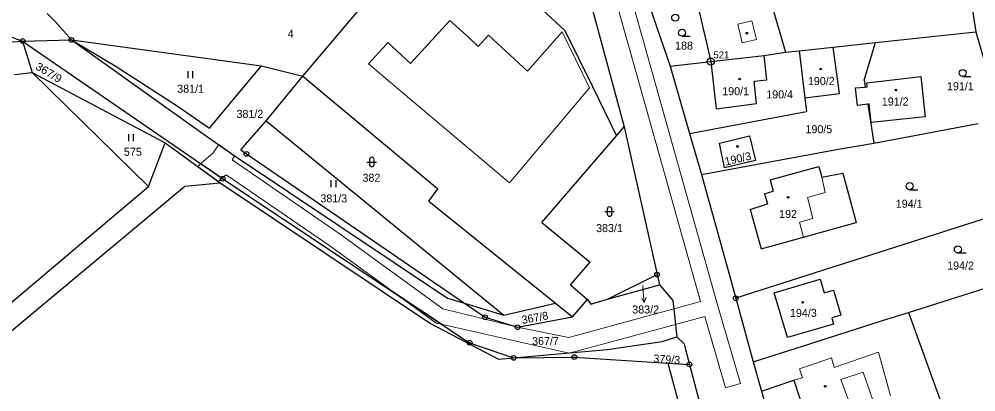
# Model space of a CAD drawing. Extents: x -633485 to -630509, y -1112692 to -1108818.
# Drawn here: x -632090.4 to -631887.2, y -1111932.7 to -1111853.5 of the extents above; entities that cross this region are included whole.
import ezdxf
from ezdxf.enums import TextEntityAlignment as Align

# ---------------------------------------------------------------- set-up
doc = ezdxf.new("R2010")
doc.units = 0
doc.header["$LTSCALE"] = 0.68
for name, color, linetype, lineweight in [('1', 7, 'Continuous', 25), ('13', 7, 'Continuous', 13), ('3', 7, 'Continuous', 25), ('4', 7, 'Continuous', 13), ('5', 7, 'Continuous', 25), ('7', 7, 'Continuous', 13), ('8', 7, 'Continuous', 25)]:
    doc.layers.add(name, color=color, linetype=linetype, lineweight=lineweight)
doc.layers.add('2', color=7, linetype='Continuous')

msp = doc.modelspace()

# ---------------------------------------------------------------- linework, layer by layer
at = {"layer": '1'}
for p, q in [((-631998.22, -1111834.02), (-631974.46, -1111855.89)), ((-631935.68, -1111832.67), (-631927.63, -1111860.54)), ((-631971.67, -1111840.26), (-631961.88, -1111876.36)), ((-632030.12, -1111865.6), (-632010.39, -1111842.25)), ((-631957.85, -1111846.76), (-631952.09, -1111863.51)), ((-631888.32, -1111848.82), (-631887.21, -1111856.22)), ((-632084.43, -1111852.32), (-632082.76, -1111853.97)), ((-631946.06, -1111851.62), (-631943.49, -1111862.52)), ((-632099.62, -1111854.48), (-632089.68, -1111858.15)), ((-632082.76, -1111853.97), (-632079.31, -1111857.93)), ((-631974.46, -1111855.89), (-631968.62, -1111867.8)), ((-631908.53, -1111858.5), (-631887.21, -1111856.22)), ((-631887.21, -1111856.22), (-631881.84, -1111874.72)), ((-632201.81, -1111865.84), (-632089.68, -1111858.15)), ((-632089.68, -1111858.15), (-632079.31, -1111857.93)), ((-632089.68, -1111858.15), (-632047.16, -1111887.42)), ((-632089.68, -1111858.15), (-632087.66, -1111864.83)), ((-632079.31, -1111857.93), (-632051.1, -1111877.99)), ((-632079.31, -1111857.93), (-632038.9, -1111863.4)), ((-632079.31, -1111857.93), (-632070, -1111863.44)), ((-631917.48, -1111859.49), (-631908.53, -1111858.5)), ((-631910.94, -1111866.46), (-631908.53, -1111858.5)), ((-631932.13, -1111861.24), (-631927.63, -1111860.54)), ((-631927.63, -1111860.54), (-631924.68, -1111860.27)), ((-631924.68, -1111860.27), (-631917.48, -1111859.49)), ((-631916.18, -1111869.33), (-631917.48, -1111859.49)), ((-632070, -1111863.44), (-632056.83, -1111871.95)), ((-632050, -1111876.68), (-632038.9, -1111863.4)), ((-632038.9, -1111863.4), (-632030.12, -1111865.6)), ((-632091.38, -1111865.28), (-632087.66, -1111864.83)), ((-632087.66, -1111864.83), (-632062.95, -1111889.09)), ((-632087.66, -1111864.83), (-632059.38, -1111879.77)), ((-632037.91, -1111875.15), (-632030.12, -1111865.6)), ((-632030.12, -1111865.6), (-632001.49, -1111889.6)), ((-631910.94, -1111866.46), (-631910.71, -1111867.94)), ((-631910.36, -1111867.01), (-631898.88, -1111865.72)), ((-631968.62, -1111867.8), (-631963.49, -1111878.29)), ((-631912.75, -1111868.12), (-631910.71, -1111867.94)), ((-631912.33, -1111871.84), (-631912.75, -1111868.12)), ((-631910.71, -1111867.94), (-631910.28, -1111867.9)), ((-631910.28, -1111867.9), (-631910.36, -1111867.01)), ((-631923.49, -1111870.22), (-631923.15, -1111873.1)), ((-632056.83, -1111871.95), (-632050, -1111876.68)), ((-631910.15, -1111871.6), (-631912.33, -1111871.84)), ((-631909.86, -1111871.57), (-631910.15, -1111871.6)), ((-631910.15, -1111871.6), (-631908.88, -1111879.83)), ((-631909.44, -1111875.46), (-631909.86, -1111871.57)), ((-632043.35, -1111881.28), (-632037.91, -1111875.15)), ((-632037.91, -1111875.15), (-631987.42, -1111916.44)), ((-631963.49, -1111878.29), (-631961.88, -1111876.36)), ((-631961.88, -1111876.36), (-631954.88, -1111907.8)), ((-631908.88, -1111879.83), (-631886.67, -1111875.7)), ((-632051.1, -1111877.99), (-632044.54, -1111882.62)), ((-631979.37, -1111896.75), (-631963.49, -1111878.29)), ((-631947.98, -1111877.8), (-631945.47, -1111886.5)), ((-632062.95, -1111889.09), (-632059.38, -1111879.77)), ((-632059.38, -1111879.77), (-632047.68, -1111888.29)), ((-631916.79, -1111881.23), (-631908.88, -1111879.83)), ((-632044.54, -1111882.62), (-631999.43, -1111912.79)), ((-632043.35, -1111881.28), (-632042.12, -1111882.14)), ((-632042.12, -1111882.14), (-631995.78, -1111913.9)), ((-631945.47, -1111886.5), (-631916.79, -1111881.23)), ((-631930.91, -1111887.65), (-631920.51, -1111884.81)), ((-631920.51, -1111884.81), (-631919.87, -1111887.08)), ((-631945.47, -1111886.5), (-631938.19, -1111912.84)), ((-631919.87, -1111887.08), (-631915.44, -1111886.26)), ((-631915.44, -1111886.26), (-631912.62, -1111896.71)), ((-632096.11, -1111923.1), (-632055.22, -1111889.02)), ((-632055.22, -1111889.02), (-632047.68, -1111888.29)), ((-632047.68, -1111888.29), (-632003.04, -1111918.16)), ((-632047.16, -1111887.42), (-631994.71, -1111922.29)), ((-631930.91, -1111887.65), (-631930.22, -1111890.09)), ((-632099.6, -1111920.09), (-632062.95, -1111889.09)), ((-632003.39, -1111892.19), (-632001.49, -1111889.6)), ((-631932.06, -1111890.61), (-631930.22, -1111890.09)), ((-631932.06, -1111890.61), (-631931.45, -1111892.78)), ((-632003.39, -1111892.19), (-631976.45, -1111913.88)), ((-631874.74, -1111892.53), (-631938.19, -1111912.84)), ((-631935.13, -1111893.95), (-631931.45, -1111892.78)), ((-631935.13, -1111893.95), (-631932.76, -1111902.35)), ((-631979.37, -1111896.75), (-631969.12, -1111905.15)), ((-631923.78, -1111899.82), (-631912.62, -1111896.71)), ((-631932.76, -1111902.35), (-631923.78, -1111899.82)), ((-631973.27, -1111909.97), (-631969.12, -1111905.15)), ((-631901.48, -1111915.84), (-631872.64, -1111906.66)), ((-631965.4, -1111913.05), (-631954.88, -1111907.8)), ((-631954.88, -1111907.8), (-631954.4, -1111909.97)), ((-631973.27, -1111909.97), (-631969.71, -1111913.06)), ((-631965.4, -1111913.05), (-631954.4, -1111909.97)), ((-631954.4, -1111909.97), (-631951.57, -1111913.27)), ((-631999.43, -1111912.79), (-631995.78, -1111913.9)), ((-631972.86, -1111916.77), (-631969.71, -1111913.06)), ((-631969.71, -1111913.06), (-631968.99, -1111914.05)), ((-631968.99, -1111914.05), (-631965.4, -1111913.05)), ((-631951.57, -1111913.27), (-631950.69, -1111921.01)), ((-631938.19, -1111912.84), (-631934.46, -1111926.33)), ((-631995.78, -1111913.9), (-631991.45, -1111916.87)), ((-631995.78, -1111913.9), (-631987.42, -1111916.44)), ((-631987.42, -1111916.44), (-631976.45, -1111913.88)), ((-631976.45, -1111913.88), (-631972.86, -1111916.77)), ((-631991.45, -1111916.87), (-631984.52, -1111918.98)), ((-631984.52, -1111918.98), (-631972.86, -1111916.77)), ((-631907, -1111917.59), (-631901.48, -1111915.84)), ((-631901.48, -1111915.84), (-631891.55, -1111943.23)), ((-632003.04, -1111918.16), (-631988.55, -1111925.79)), ((-631923.82, -1111922.95), (-631907, -1111917.59)), ((-631953.83, -1111922.04), (-631950.69, -1111921.01)), ((-631950.69, -1111921.01), (-631949.16, -1111922.53)), ((-631994.71, -1111922.29), (-631985.37, -1111925.51)), ((-631965.48, -1111923.75), (-631953.83, -1111922.04)), ((-631949.16, -1111922.53), (-631948.85, -1111923.69)), ((-631934.46, -1111926.33), (-631923.82, -1111922.95)), ((-631988.55, -1111925.79), (-631985.37, -1111925.51)), ((-631985.37, -1111925.51), (-631965.48, -1111923.75)), ((-631985.37, -1111925.51), (-631972.49, -1111925.33)), ((-631972.49, -1111925.33), (-631952.6, -1111926.6)), ((-631948.85, -1111923.69), (-631948.02, -1111926.89)), ((-631952.6, -1111926.6), (-631948.02, -1111926.89)), ((-631952.6, -1111926.6), (-631946.86, -1111947.99)), ((-631948.02, -1111926.89), (-631914.27, -1112055.54)), ((-631934.46, -1111926.33), (-631932.7, -1111932.56)), ((-631932.7, -1111932.56), (-631925.86, -1111930.24)), ((-631925.86, -1111930.24), (-631922.8, -1111939.4)), ((-631932.7, -1111932.56), (-631926.51, -1111954.39))]:
    msp.add_line(p, q, dxfattribs=at)
for points in [[(-631924.68, -1111860.27), (-631923.49, -1111870.22), (-631916.18, -1111869.33)], [(-631952.09, -1111863.51), (-631943.49, -1111862.52), (-631932.13, -1111861.24)], [(-631943.49, -1111862.52), (-631942.36, -1111872.57), (-631933.76, -1111871.46), (-631934.3, -1111866.72), (-631931.55, -1111866.41), (-631932.13, -1111861.24)], [(-631952.09, -1111863.51), (-631947.98, -1111877.8), (-631923.15, -1111873.1)], [(-631898.88, -1111865.72), (-631897.93, -1111874.24), (-631909.44, -1111875.46)], [(-631927.19, -1111921.2), (-631930.04, -1111911.66), (-631920.24, -1111908.77), (-631919.38, -1111911.7)], [(-631919.38, -1111911.7), (-631917.41, -1111911.11), (-631915.84, -1111916.43), (-631917.8, -1111917.01)], [(-631917.8, -1111917.01), (-631917.43, -1111918.3), (-631927.19, -1111921.2)]]:
    msp.add_lwpolyline(points, dxfattribs=at)
msp.add_lwpolyline([(-631940.59, -1111885.13), (-631941.67, -1111879.84), (-631935.25, -1111878.27), (-631933.97, -1111883.52)], close=True, dxfattribs=at)
at = {"layer": '13'}
msp.add_lwpolyline([(-631964.38, -1111846.95), (-631945.65, -1111913.51), (-631951.36, -1111915.07), (-631973.62, -1111921.16), (-631984.52, -1111918.98), (-632000.44, -1111915.07), (-632022.45, -1111899.05), (-632045.19, -1111883.43), (-632044.64, -1111882.55), (-632048.01, -1111880.17), (-632049.18, -1111881.9), (-632051.82, -1111884.21), (-632047.32, -1111887.31), (-632046.46, -1111886.56), (-632024.39, -1111901.71), (-632010.98, -1111911.47), (-632000.49, -1111918.44), (-631973.56, -1111924.47), (-631950.99, -1111918.37), (-631944.76, -1111916.68), (-631940.37, -1111931.88), (-631937.2, -1111930.96), (-631942.03, -1111914.22), (-631961.2, -1111846.09)], dxfattribs=at)
for points in [[(-632052.48, -1111884.79), (-632048.09, -1111887.99), (-632047.32, -1111887.31), (-632051.82, -1111884.21)], [(-632010.98, -1111911.47), (-632001.81, -1111918.15), (-632000.49, -1111918.44)]]:
    msp.add_lwpolyline(points, close=True, dxfattribs=at)
at = {"layer": '3'}
for p, q in [((-631949.593, -1111857.14), (-631947.843, -1111857.14)), ((-632054.491, -1111866.03), (-632054.491, -1111864.53)), ((-632053.49, -1111866.03), (-632053.49, -1111864.53)), ((-631889.993, -1111865.69), (-631888.243, -1111865.69)), ((-632067.111, -1111879.43), (-632067.111, -1111877.93)), ((-632066.11, -1111879.43), (-632066.11, -1111877.93)), ((-632016.521, -1111883.871), (-632014.519, -1111883.871)), ((-632016.021, -1111883.371), (-632016.021, -1111884.372)), ((-632015.019, -1111884.372), (-632015.019, -1111883.371)), ((-632024.101, -1111889.2), (-632024.101, -1111887.7)), ((-632023.1, -1111889.2), (-632023.1, -1111887.7)), ((-631901.253, -1111889.75), (-631899.503, -1111889.75)), ((-631966.001, -1111894.401), (-631963.999, -1111894.401)), ((-631965.501, -1111893.901), (-631965.501, -1111894.902)), ((-631964.499, -1111894.902), (-631964.499, -1111893.901)), ((-631890.993, -1111903.2), (-631889.243, -1111903.2))]:
    msp.add_line(p, q, dxfattribs=at)
for centre in [(-631949.5929, -1111856.3898), (-631889.9929, -1111864.9398), (-631901.2529, -1111888.9998), (-631890.9929, -1111902.4498)]:
    msp.add_circle(centre, 0.75, dxfattribs=at)
for centre, start, end in [((-632015.52, -1111883.3709), 0, 180), ((-632015.52, -1111884.3709), 180, 359.98789), ((-631965, -1111893.9009), 0, 180), ((-631965, -1111894.9009), 180, 359.98789)]:
    msp.add_arc(centre, 0.5, start, end, dxfattribs=at)
at = {"layer": '4'}
for p, q in [((-631937.75, -1111854.57), (-631934.75, -1111853.86)), ((-631934.75, -1111853.86), (-631933.8, -1111857.84)), ((-631982.42, -1111864.54), (-631975.08, -1111856.2)), ((-631975.08, -1111856.2), (-631969.25, -1111868.11)), ((-631937.75, -1111854.57), (-631936.8, -1111858.56)), ((-631994.92, -1111857.44), (-631992.9, -1111859.3)), ((-631992.9, -1111859.3), (-631990.71, -1111856.92)), ((-631990.71, -1111856.92), (-631982.42, -1111864.54)), ((-631936.8, -1111858.56), (-631933.8, -1111857.84)), ((-632016.21, -1111862.98), (-632005.62, -1111871.92)), ((-631986.26, -1111888.26), (-631969.25, -1111868.11)), ((-632005.62, -1111871.92), (-631986.26, -1111888.26)), ((-631919.87, -1111887.08), (-631919.2, -1111890.37)), ((-631922.96, -1111891.4), (-631919.2, -1111890.37)), ((-631922.96, -1111891.4), (-631921.8, -1111895.91)), ((-631924.66, -1111896.69), (-631921.8, -1111895.91)), ((-631924.66, -1111896.69), (-631923.78, -1111899.82)), ((-631922.51, -1111927.13), (-631917.88, -1111925.46)), ((-631917.88, -1111925.46), (-631917.28, -1111927.57)), ((-631917.28, -1111927.57), (-631907.85, -1111924.27)), ((-631907.85, -1111924.27), (-631905.28, -1111933.59)), ((-631924.62, -1111927.83), (-631922.51, -1111927.13)), ((-631924.62, -1111927.83), (-631923.98, -1111929.76)), ((-631915.87, -1111930.08), (-631911.11, -1111928.56)), ((-631911.11, -1111928.56), (-631908.89, -1111934.89)), ((-631925.86, -1111930.24), (-631923.98, -1111929.76)), ((-631915.87, -1111930.08), (-631913.5, -1111936.43))]:
    msp.add_line(p, q, dxfattribs=at)
msp.add_lwpolyline([(-631994.92, -1111857.44), (-631998.89, -1111853.79), (-632007.28, -1111862.9), (-632012.08, -1111858.48), (-632012.46, -1111858.9), (-632016.21, -1111862.98)], dxfattribs=at)
at = {"layer": '5'}
for centre in [(-631935.8468, -1111856.4892), (-631920.1368, -1111864.1092), (-631937.3368, -1111866.2292), (-631904.1268, -1111868.5792), (-631937.8168, -1111880.5592), (-631927.0668, -1111891.3792), (-631923.9868, -1111913.6792), (-631919.1768, -1111931.5492)]:
    msp.add_circle(centre, 0.175, dxfattribs=at)
at = {"layer": '7'}
msp.add_line((-631957.638, -1111913.7), (-631957.227, -1111912.658), dxfattribs=at)
msp.add_lwpolyline([(-631957.95, -1111910.11), (-631957.9, -1111910.71), (-631957.638, -1111913.7), (-631958.225, -1111912.746)], dxfattribs=at)
at = {"layer": '8'}
for centre, radius in [((-631951.04, -1111853.1798), 0.75), ((-632089.68, -1111858.1499), 0.5), ((-632089.68, -1111858.1499), 0.0303), ((-632079.31, -1111857.9299), 0.5), ((-632079.31, -1111857.9299), 0.0303), ((-631943.49, -1111862.5198), 0.75), ((-631943.49, -1111862.5198), 0.03), ((-632042.12, -1111882.1399), 0.5), ((-632042.12, -1111882.1399), 0.0303), ((-632047.16, -1111887.4199), 0.5), ((-632047.16, -1111887.4199), 0.0303), ((-631954.88, -1111907.7999), 0.5), ((-631954.88, -1111907.7999), 0.0303), ((-631938.19, -1111912.8399), 0.5), ((-631938.19, -1111912.8399), 0.0303), ((-631991.45, -1111916.8699), 0.5), ((-631991.45, -1111916.8699), 0.0303), ((-631984.52, -1111918.9799), 0.5), ((-631984.52, -1111918.9799), 0.0303), ((-631994.71, -1111922.2899), 0.5), ((-631994.71, -1111922.2899), 0.0303), ((-631985.37, -1111925.5099), 0.5), ((-631985.37, -1111925.5099), 0.0303), ((-631972.49, -1111925.3299), 0.5), ((-631972.49, -1111925.3299), 0.0303), ((-631948.02, -1111926.8899), 0.5), ((-631948.02, -1111926.8899), 0.0303)]:
    msp.add_circle(centre, radius, dxfattribs=at)

# ---------------------------------------------------------------- texts
at = {"layer": '2'}
for s, p in [('4', (-632033.35, -1111857.435)), ('188', (-631951.07, -1111859.975)), ('381/1', (-632056.83, -1111869.145)), ('381/2', (-632044.24, -1111874.495)), ('575', (-632068.15, -1111882.545)), ('382', (-632017.48, -1111888.075)), ('381/3', (-632026.42, -1111892.445)), ('194/1', (-631904.19, -1111893.585)), ('192', (-631928.97, -1111895.755)), ('383/1', (-631967.85, -1111898.765)), ('194/2', (-631893.28, -1111906.725)), ('367/7', (-631981.45, -1111922.775))]:
    msp.add_text(s, height=1.7, dxfattribs=at).set_placement(p)
at = {"layer": '2', "width": 1.05}
msp.add_text('367/9', height=1.7, rotation=329, dxfattribs=at).set_placement((-632087.108, -1111864.044))
at = {"layer": '2'}
for s, p in [('190/2', (-631920.01, -1111867.515)), ('190/1', (-631938.21, -1111869.665)), ('190/4', (-631928.86, -1111870.345)), ('191/1', (-631890.47, -1111868.612)), ('191/2', (-631904.31, -1111871.862)), ('190/5', (-631920.53, -1111877.742)), ('383/2', (-631957.32, -1111916.065)), ('194/3', (-631923.82, -1111916.785))]:
    msp.add_text(s, height=1.7, dxfattribs=at).set_placement(p, align=Align.CENTER)
msp.add_text('190/3', height=1.7, rotation=13, dxfattribs=at).set_placement((-631937.5462, -1111883.9815), align=Align.CENTER)
for s, rotation, p in [('367/8', 10, (-631983.496, -1111918.288)), ('379/3', 356, (-631955.729, -1111926.453))]:
    msp.add_text(s, height=1.7, rotation=rotation, dxfattribs=at).set_placement(p)
at = {"layer": '8'}
msp.add_text('521', height=1.5, dxfattribs=at).set_placement((-631942.92, -1111861.835))

doc.saveas('drawing.dxf')
